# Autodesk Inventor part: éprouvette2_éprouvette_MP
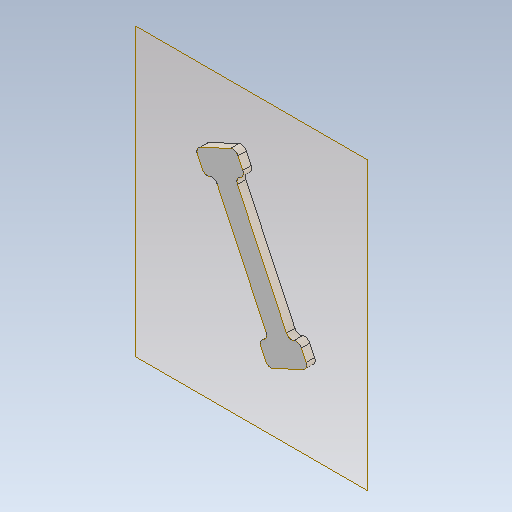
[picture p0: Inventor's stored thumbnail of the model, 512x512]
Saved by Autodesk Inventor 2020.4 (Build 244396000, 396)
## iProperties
Created: 2021-10
Part Number: éprouvette2_éprouvette_MP
Material: Générique
Document SubType Name: Modeling
Designer: mel
Density: 1 g/cm^3
Appearance: Par défaut
Author: mel
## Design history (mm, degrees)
derived "éprouvette.ipt"
node "éprouvette2_éprouvette_WP"
node "Plan de construction1"
sketch "Esquisse1"
  geometry: L1 (28.902, -34.154)-(28.902, 67.846); L2 (28.902, 67.846)-(-53.598, 67.846); L3 (-53.598, 67.846)-(-53.598, -34.154); L4 (-53.598, -34.154)-(28.902, -34.154); L5 (0, 0)-(-17.457, 37.098) reference; L6 (-15.541, 42.42)-(-17.244, 46.04) reference; L7 (-19.905, 46.998)-(-30.763, 41.888) reference; L8 (-31.721, 39.227)-(-30.018, 35.608) reference; L9 (-24.696, 33.692)-(-7.239, -3.406) reference; L10 (-9.155, -8.729)-(-7.452, -12.348) reference; L11 (-4.79, -13.306)-(6.067, -8.197) reference; L12 (7.026, -5.535)-(5.322, -1.916) reference; A1 r 2 centre (-15.647, 37.949) between (-16.499, 39.759) and (-17.457, 37.098) reference; A2 r 2 centre (-17.35, 41.569) between (-16.499, 39.759) and (-15.541, 42.42) reference; A3 r 2 centre (-19.054, 45.188) between (-17.244, 46.04) and (-19.905, 46.998) reference; A4 r 2 centre (-29.911, 40.079) between (-30.763, 41.888) and (-31.721, 39.227) reference; A5 r 2 centre (-28.208, 36.459) between (-30.018, 35.608) and (-27.357, 34.65) reference; A6 r 2 centre (-26.505, 32.84) between (-24.696, 33.692) and (-27.357, 34.65) reference; A7 r 2 centre (-9.048, -4.258) between (-8.197, -6.067) and (-7.239, -3.406) reference; A8 r 2 centre (-7.345, -7.877) between (-8.197, -6.067) and (-9.155, -8.729) reference; A9 r 2 centre (-5.642, -11.496) between (-7.452, -12.348) and (-4.79, -13.306) reference; A10 r 2 centre (5.216, -6.387) between (6.067, -8.197) and (7.026, -5.535) reference; A11 r 2 centre (3.513, -2.768) between (5.322, -1.916) and (2.661, -0.958) reference; A12 r 2 centre (1.81, 0.852) between (0, 0) and (2.661, -0.958) reference; 1 further point
  constraints: 8 end point
  dimensions: "d7" = 41.25 horizontal distance of point (-12.348, 16.846) L1.end (= 1.5 x Xmax); "d8" = 51 vertical distance of point (-12.348, 16.846) L1.end (= 1.5 x Ymax); "d9" = 41.25 horizontal distance of point (-12.348, 16.846) L2.end (= -1.5 x Xmin); "d10" = 51 vertical distance of point (-12.348, 16.846) L2.end (= 1.5 x Ymax); "d11" = 41.25 horizontal distance of point (-12.348, 16.846) L3.end (= -1.5 x Xmin); "d12" = 51 vertical distance of point (-12.348, 16.846) L3.end (= -1.5 x Ymin); "d13" = 41.25 horizontal distance of point (-12.348, 16.846) L1.start (= 1.5 x Xmax); "d14" = 51 vertical distance of point (-12.348, 16.846) L1.start (= -1.5 x Ymin)
feature "Carreau délimité1" sketch "Esquisse1"
feature "Séparation d'empreinte1"
feature "Solide1::éprouvette.ipt"
tag "FonctionRepérage1"
feature "Solide1::éprouvette2_éprouvette_WP"
tag "FonctionRepérage2"
body "Srf1"
node "Solide3"
node "Solide4"
node "Solide1"
feature "éprouvette.ipt_Corps"
node "Solide2"
feature "éprouvette2_éprouvette_WP_Corps"
other parameters: "d0" = -25, "d1" = 27.5, "d2" = 27.5, "d3" = 34, "d4" = 34, "d6" = 0, "Xmin" = -27.5, "Ymin" = -34, "Zmin" = -25, "Xmax" = 27.5, "Ymax" = 34, "Zmax" = 25
